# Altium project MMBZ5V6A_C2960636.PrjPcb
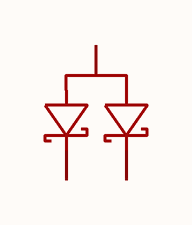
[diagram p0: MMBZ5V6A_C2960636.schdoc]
1 sheet, 1 parts. Net scope: global (net labels, ports and power ports of the same name join across sheets).

## Sheet MMBZ5V6A_C2960636.schdoc
size 127 x 101 mm

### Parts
U?  mmbz5v6a  [SOT-23-3_L2.9-W1.3-P1.90-LS2.4-BR]  (value not drawn)

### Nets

Not connected (* = marked no-connect by the designer): U? 1 2 3

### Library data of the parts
U? = mmbz5v6a: 极性:单向;反向截止电压(Vrwm):3V;钳位电压:8V;峰值脉冲电流(Ipp):3A;峰值脉冲功率(Ppp):24W;击穿电压(VBR):5.32V;; Manufacturer: JSMSEMI(杰盛微); Symbol: MMBZ5V6A_C2960636; AddInBom: yes; ModelId: c62791f0466c4ae2a892c056b845b0ca; ModelName: SOT-23-3P_L2.9-W1.3-H1.0-LS2.4-P0.95; ModelTransform: 98.425,114.173,0,180,0,0,0.0005,-0.0005,0; Polarity: 单向; Reverse Stand-Off Voltage (Vrwm): 3V; Clamping Voltage: 8V; Peak Pulse Current (Ipp): 3A; Peak Pulse Power Dissipation (Ppp): 24W; Voltage - Breakdown: 5.32V; Reverse Leakage Current (Ir): 5uA; Number of Channels: 双路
